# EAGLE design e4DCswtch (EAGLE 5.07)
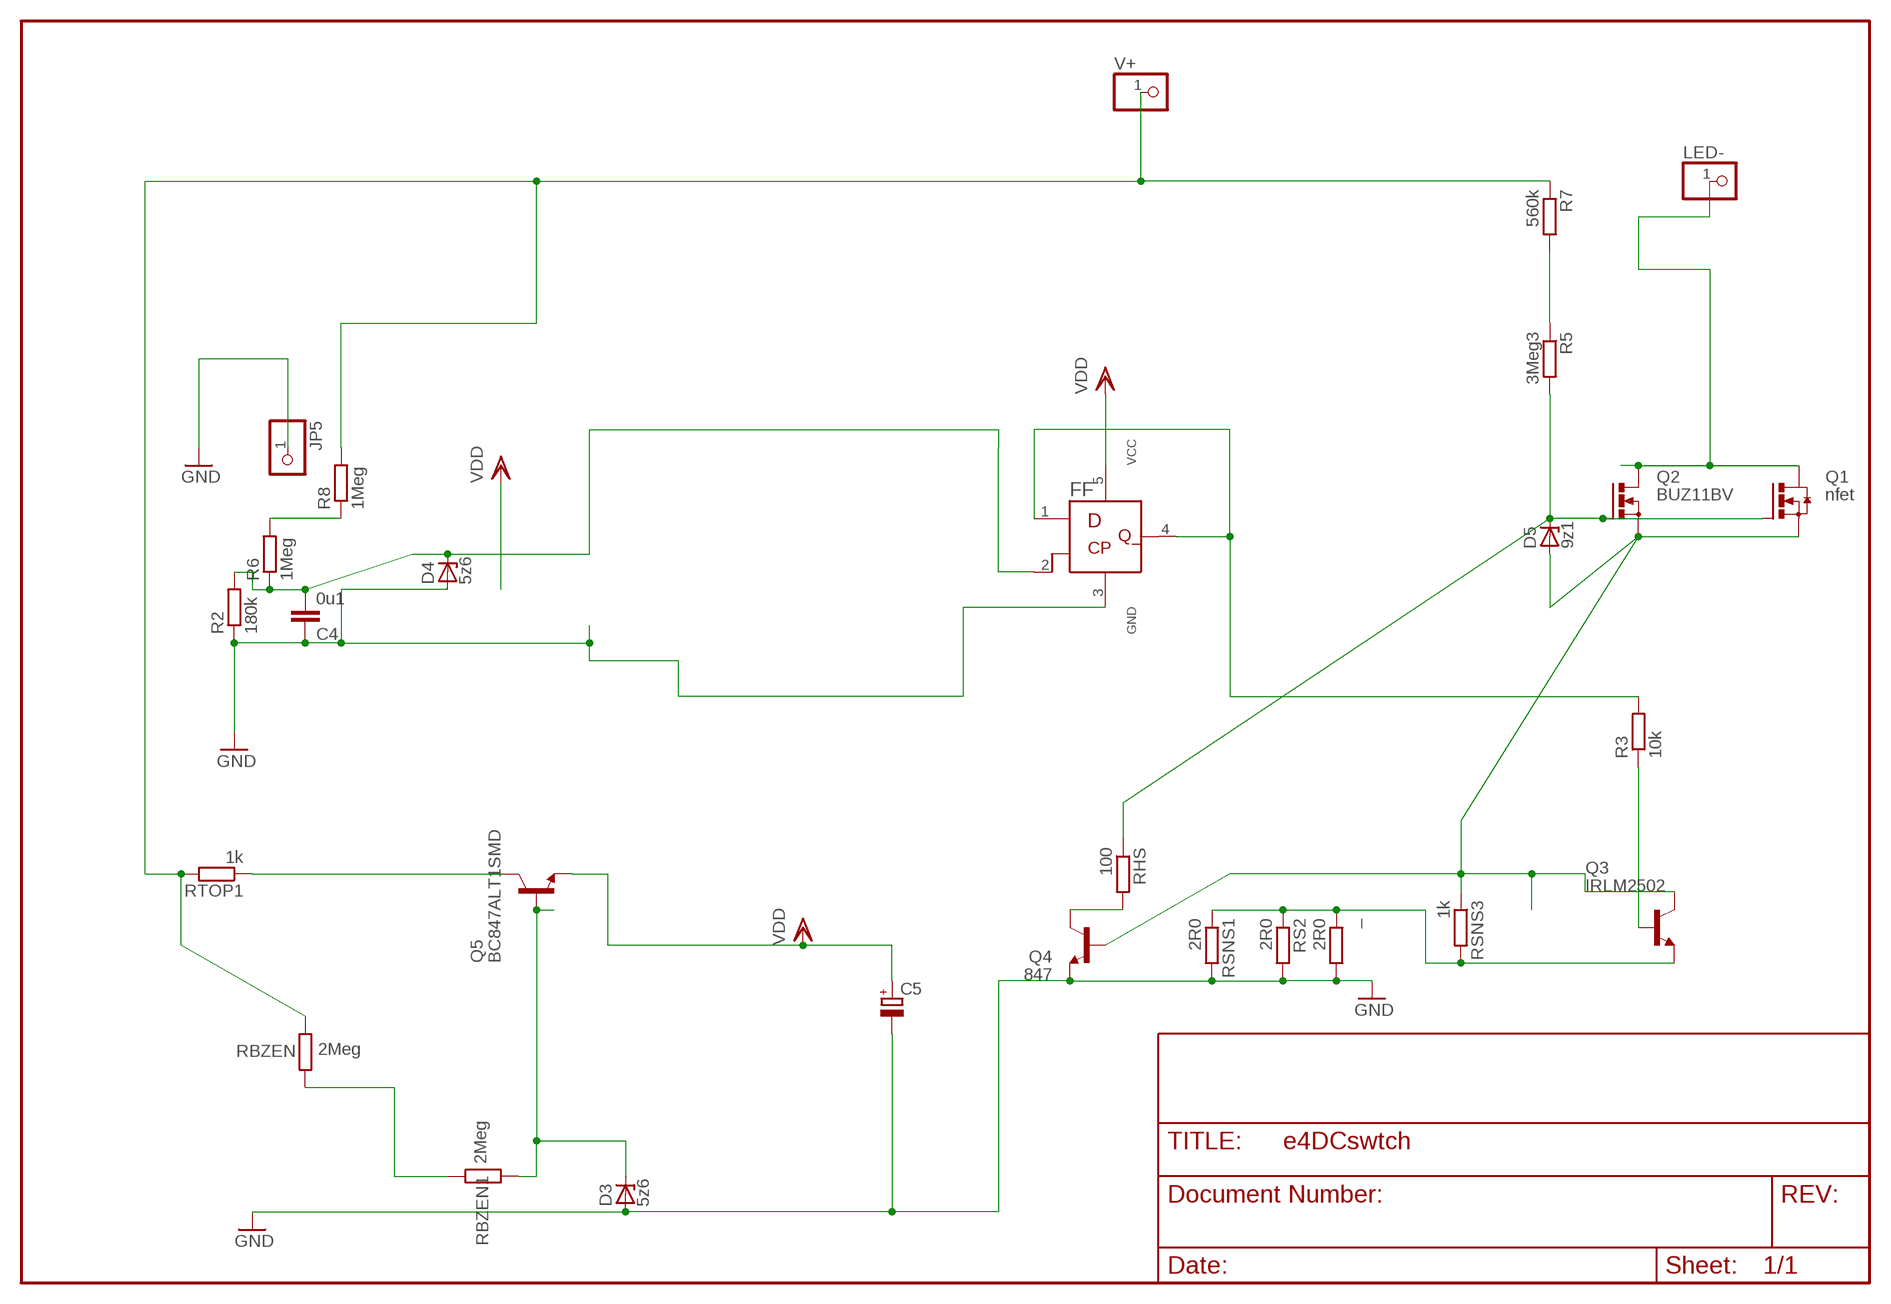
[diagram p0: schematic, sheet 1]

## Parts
_  2R0  R-EU_R2010  [R2010]
C4  0u1  C-EUC1206  [C1206]
C5  CPOL-EUSMCA  [SMC_A]
D3  5z6  ZENER-DIODESOD80C  [SOD80C]
D4  5z6  ZENER-DIODESOD80C  [SOD80C]
D5  9z1  ZENER-DIODESOD80C  [SOD80C]
FF  7479SOT23  [SOT23-5]
JP5  PINHD-1X11MM6  [1X1MM8]
LED-  PINHD-1X11MM6  [1X1MM8]
Q1  nfet  N-HEXFET_DPAK-  [TO252]
Q2  BUZ11BV  [TO220BV]
Q3  IRLM2502  BC847ALT1SMD  [SOT23]
Q4  847  BC847ASMD  [SOT23]
Q5  BC847ALT1SMD  [SOT23]
R2  180k  R-EU_R0805  [R0805]
R3  10k  R-EU_R0805  [R0805]
R5  3Meg3  R-EU_R1206  [R1206]
R6  1Meg  R-EU_R1206  [R1206]
R7  560k  R-EU_R1206  [R1206]
R8  1Meg  R-EU_R1206  [R1206]
RBZEN  2Meg  R-EU_R1206  [R1206]
RBZEN1  2Meg  R-EU_R1206  [R1206]
RHS  100  R-EU_0204/5  [0204/5]
RS2  2R0  R-EU_R1206  [R1206]
RSNS1  2R0  R-EU_R2512  [R2512]
RSNS3  1k  R-EU_R1206  [R1206]
RTOP1  1k  R-EU_R1206  [R1206]
V+  PINHD-1X11MM6  [1X1MM8]

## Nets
BSW1: _.1 Q3.2(E) RS2.1 RSNS1.1 RSNS3.2
C: Q5.3(C) RTOP1.1
CB: D3.C Q5.1(B) RBZEN1.2
GND: _.2 C4.1 C5.- D3.A D4.A FF.3(GND) JP5.1 Q4.2(E) R2.1 RS2.2 RSNS1.2
LED-: LED-.1 Q1.3(D) Q2.D
N$1: D5.C Q1.1(G) Q2.G R5.2 RHS.1
N$2: FF.1(D) FF.4(Q_) R3.2
N$3: C4.2 D4.C FF.2(CP) R2.2 R6.1
N$4: R5.1 R7.2
N$5: Q3.1(B) R3.1
N$6: RBZEN1.1 RBZEN.2
N$7: Q4.3(C) RHS.2
N$9: R6.2 R8.1
S: D5.A Q1.2(S) Q2.S Q3.3(C) Q4.1(B) RSNS3.1
VDD: C5.+ FF.5(VCC) Q5.2(E)
VPLUS: R7.1 R8.2 RBZEN.1 RTOP1.2 V+.1

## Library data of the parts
_ R3 R5 R7 RBZEN RBZEN1 RHS RS2 RSNS1 RSNS3 RTOP1 = rcl:R-EU_: RESISTOR, European symbol
C4 = rcl:C-EU: CAPACITOR, European symbol
C5 = rcl-2:CPOL-EU: POLARIZED CAPACITOR, European symbol
D3-D5 = diode:ZENER-DIODE: Z-Diode
FF = 74xx-little-de:7479
JP5 LED- V+ = pinhead:PINHD-1X1: PIN HEADER
Q1 = transistor-power:N-HEXFET_?-*: HEXFET® Power MOSFET
Q2 = transistor-power:BUZ11: N-CHANNEL MOS FET
Q3-Q5 = transistor-npn:BC847*: NPN Transistor
R2 R6 R8 = rcl-2:R-EU_: RESISTOR, European symbol

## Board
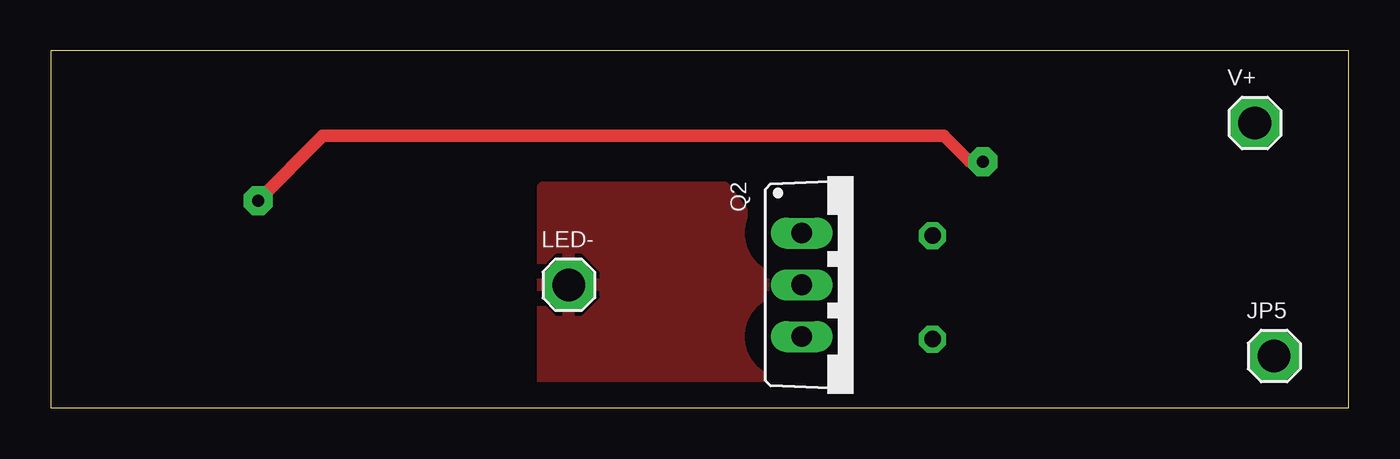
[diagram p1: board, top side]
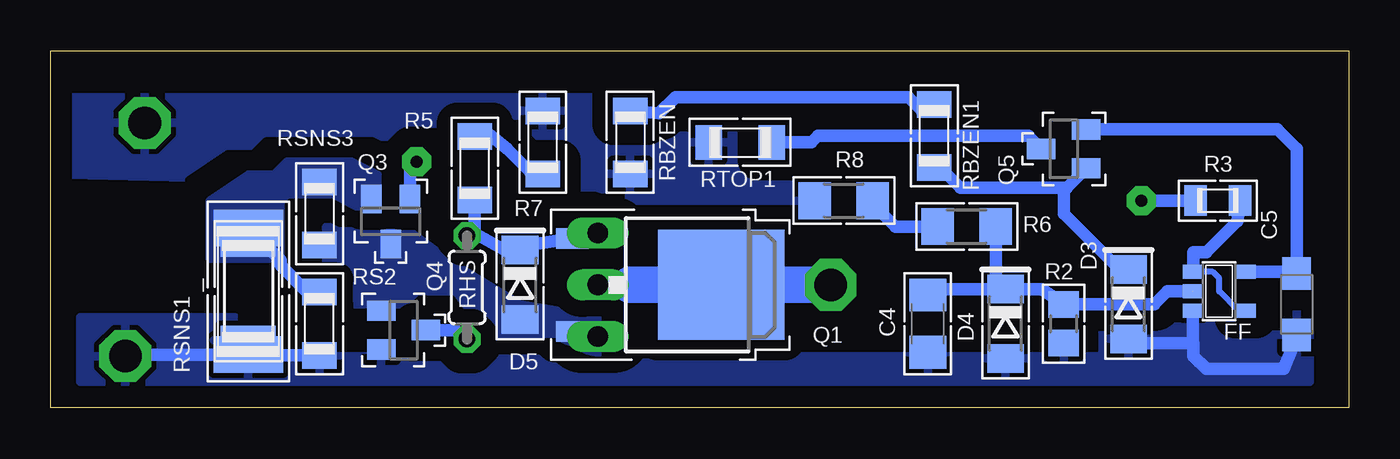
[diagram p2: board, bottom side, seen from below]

Size 63.66 x 17.5 mm. Coordinates in mm from the lower left corner, seen from the top.
Outline: 0,0 63.66,0 63.66,17.5 0,17.5 0,0
Copper layers (1*16): Top 0.035mm / dielectric 1.5mm / Bottom 0.035mm
Design rules "default *": minimum track width 10mil, minimum drill 24mil, track to track 8mil, track to pad 8mil, pad to pad 8mil, via to via 8mil, smd to smd 8mil, copper to edge 20mil, drill to drill 8mil, minimum pad ring 10mil, minimum via ring 8mil, stop-mask expansion 4mil, vias tented up to drill 0mil, thermal gap 10mil

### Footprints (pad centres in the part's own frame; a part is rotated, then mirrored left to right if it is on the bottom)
R2010 = smd 1.4 x 2.7: 1 -2.4,0; 2 2.4,0
C1206 = smd 1.6 x 1.8: 1 -1.4,0; 2 1.4,0
SMC_A = smd 1.6 x 1.4: + -1.5,0; - 1.5,0
SOD80C = smd 1.4 x 1.8: A 1.7,0; C -1.7,0
SOT23-5 = smd 0.69 x 0.99: 1 -0.95,-1.29; 2 0,-1.29; 3 0.95,-1.29; 4 0.95,1.3; 5 -0.95,1.3
1X1MM8 = drill 1.6 pad 2.54 octagon: 1 0,0
TO252 = smd 1 x 1.6: 1 -2.28,-3.53; 2 2.28,-3.53 | smd 5.4 x 6.2: 3 0,3.77
TO220BV = drill 1.016 long: D 0,-2.54; G -2.54,-2.54; S 2.54,-2.54
SOT23 = smd 1 x 1.4: 1 -0.95,-1.1; 2 0.95,-1.1; 3 0,1.1
R0805 = smd 1.3 x 1.5: 1 -0.95,0; 2 0.95,0
R0805' = smd 1.1 x 1.5: 1 -1.1,0; 2 1.1,0
R1206 = smd 1.3 x 1.7: 1 -1.55,0; 2 1.55,0
R1206' = smd 1.6 x 1.803: 1 -1.422,0; 2 1.422,0
0204/5 = drill 0.813 octagon: 1 -2.54,0; 2 2.54,0
R2512 = smd 1.8 x 3.4: 1 -3.1,0; 2 3.1,0

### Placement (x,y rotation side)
_  53.98,5.71 270 bottom
C4  20.64,4.13 90 bottom
C5  2.54,5.08 270 bottom
D3  10.79,5.08 270 bottom
D4  16.83,4.13 270 bottom
D5  40.64,6.03 270 bottom
FF  6.35,5.71 270 bottom
JP5  60.01,2.54 0 top
LED-  25.4,6.03 0 top
Q1  34.54,6.03 270 bottom
Q2  39.37,6.03 270 top
Q3  46.99,9.14 180 bottom
Q4  46.35,3.81 270 bottom
Q5  13.97,12.7 90 bottom
R2  13.97,4.13 90 bottom
R3  10k  [R0805']  6.41,10.16 0 bottom
R5  42.86,11.75 270 bottom
R6  1Meg  [R1206']  18.73,8.89 180 bottom
R7  39.53,13.02 270 bottom
R8  1Meg  [R1206']  24.77,10.16 180 bottom
RBZEN  35.24,13.02 90 bottom
RBZEN1  20.32,13.34 270 bottom
RHS  43.24,5.91 270 bottom
RS2  50.48,4.13 270 bottom
RSNS1  53.98,5.71 270 bottom
RSNS3  50.48,9.53 90 bottom
RTOP1  29.84,13.02 180 bottom
V+  59.05,13.97 0 top

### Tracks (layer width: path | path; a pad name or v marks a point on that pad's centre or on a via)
BSW1
  Bottom 0.61: RS2.1 51.08,5.68 52.39,6.99 52.39,7.23 RSNS1.1
  pour Bottom (isolate 0.813, rank 2, no thermals): 55.88,7.3 55.88,10.16 53.98,11.43 52.7,11.43 52.07,12.06 48.9,12.06 47.62,11.43 47.62,10.16 48.58,9.84 49.85,10.48 52.07,10.48 52.39,10.16 52.39,7.3
C
  Bottom 0.61: RTOP1.1 26.35,13.02 26.04,13.34 15.71,13.34 Q5.3
CB
  Bottom 0.61: RBZEN1.2 20.17,11.91 19.05,10.79 13.97,10.79 | 13.97,10.79 13.82,10.79 Q5.1 | D3.C 11.22,6.78 13.97,9.53 13.97,10.79
GND
  Bottom 0.61: FF.3 7.64,3.19 7.62,3.17 | 7.62,3.17 10.59,3.17 D3.A | C5.- 2.77,2.94 3.17,1.91 6.99,1.91 7.62,2.54 7.62,3.17 | RSNS1.2 _.2 | RS2.2 53.98,2.58 RSNS1.2 | RSNS1.2 60.01,2.62 JP5.1
  pour Bottom (isolate 1.016): 54.61,4.45 62.23,4.45 62.23,1.27 1.91,1.27 1.91,5.08 10.79,5.08 12.06,3.81 12.06,2.54 55.24,2.54
LED-
  Bottom 0.61: 35.24,6.03 Q2.D | Q1.3 25.53,5.59 LED-.1
  Bottom 1.778: LED-.1 35.24,6.03
  pour Top (isolate 1.27): 24.13,10.79 33.02,10.79 34.92,8.26 34.92,1.27 24.13,1.27
N$1
  Bottom 0.61: 42.86,8.57 R5.2 | 42.86,8.57 RHS.1 | Q2.G 37.37,8.57 Q1.1 40.89,7.87 D5.C 41.39,7.73 42.86,8.57
N$2
  Bottom 0.305: FF.4 5.4,4.76 6.35,5.71 6.35,6.35 6.67,6.67 FF.1
  Bottom 0.61: R3.2 5.46,9.14 6.99,7.62 7.62,7.62 7.62,6.68 FF.1
N$3
  Bottom 0.61: R6.1 17.31,6.31 D4.C | D4.C 20.34,5.83 C4.2 | D4.C 15.04,5.83 R2.2 13.65,5.08 9.53,5.08 8.89,5.71 FF.2
N$4
  Bottom 0.61: R7.2 40.17,11.6 41.27,12.7 42.08,13.34 R5.1
N$5  (via drill 0.6 pad 1.42)
  Top 0.61: v45.72,12.06 45.09,12.06 43.81,13.34 13.34,13.34 v10.16,10.16
  Bottom 0.61: Q3.1 46.04,11.74 v45.72,12.06 | R3.1 v10.16,10.16
N$6
  Bottom 0.61: RBZEN.2 33.82,14.44 33.02,15.24 21.59,15.24 20.95,14.61 20.47,14.61 RBZEN1.1
N$7
  Bottom 0.61: Q4.3 43.81,3.81 RHS.2
N$9
  Bottom 0.61: R8.1 23.5,10.16 22.23,8.89 R6.2
S
  Bottom 0.61: Q1.2 37.01,3.31 Q2.S
  pour Bottom (isolate 0.813, rank 3, no thermals): 36.83,4.45 40.64,5.08 43.81,6.99 46.35,8.89 50.16,8.89 50.16,6.35 48.9,5.08 46.35,5.08 45.72,5.71 43.81,5.71 41.91,3.17 36.83,2.54
VDD
  Bottom 0.61: Q5.2 3.49,13.65 2.54,12.7 C5.+ 2.54,6.67 FF.5
VPLUS
  pour Bottom (isolate 1.016, rank 3): 27.94,13.34 34.29,13.34 34.29,15.24 62.87,15.24 62.87,11.43 36.83,10.79 34.92,10.16 26.67,10.16 26.67,11.43 27.94,11.43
